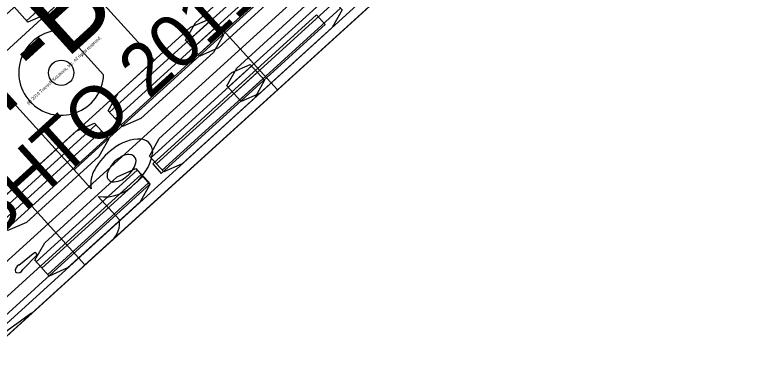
# Model space of a CAD drawing. Extents: x 1639988 to 1641860, y 841974 to 844187.
# Drawn here: x 1640775.68 to 1640795.46, y 844100.65 to 844109.81 of the extents above; entities that cross this region are included whole.
import ezdxf

# ---------------------------------------------------------------- set-up
doc = ezdxf.new("R2010")
doc.units = 0
for name, color, linetype in [('Scratch_Level_1', 7, 'Continuous'), ('Scratch_Level_2', 7, 'Continuous'), ('Scratch_Level_3', 7, 'Continuous'), ('Scratch_Level_4', 7, 'Continuous'), ('Scratch_Level_5', 7, 'Continuous'), ('Scratch_Level_6', 7, 'Continuous')]:
    doc.layers.add(name, color=color, linetype=linetype)

msp = doc.modelspace()

# ---------------------------------------------------------------- linework, layer by layer
at = {"layer": 'Scratch_Level_1'}
for p, q in [((1640777.573, 844103.088), (1640809.032, 844131.664)), ((1640776.003, 844109.65), (1640778.717, 844112.115)), ((1640777.514, 844110.713), (1640770.05, 844103.933)), ((1640779.442, 844108.591), (1640777.514, 844110.713)), ((1640778.239, 844107.189), (1640780.953, 844109.654)), ((1640778.393, 844107.019), (1640781.107, 844109.484)), ((1640771.858, 844109.38), (1640777.573, 844103.088)), ((1640778.077, 844108.196), (1640776.991, 844109.393)), ((1640778.547, 844106.849), (1640781.261, 844109.315)), ((1640771.978, 844101.811), (1640779.442, 844108.591)), ((1640779.348, 844105.967), (1640782.062, 844108.433)), ((1640779.502, 844105.798), (1640782.216, 844108.263)), ((1640779.656, 844105.628), (1640782.37, 844108.093)), ((1640775.155, 844104.387), (1640777.869, 844106.852)), ((1640775.309, 844104.217), (1640778.023, 844106.683)), ((1640775.463, 844104.048), (1640778.177, 844106.513)), ((1640776.264, 844103.166), (1640778.978, 844105.631)), ((1640776.418, 844102.996), (1640779.132, 844105.461)), ((1640776.572, 844102.826), (1640779.286, 844105.292)), ((1640777.573, 844103.088), (1640777.573, 844103.088))]:
    msp.add_line(p, q, dxfattribs=at)
msp.add_lwpolyline([(1640808.793, 844131.447), (1640706.365, 844038.416), (1640702.379, 844034.843), (1640698.36, 844031.302), (1640694.302, 844027.802), (1640690.201, 844024.347), (1640686.055, 844020.942), (1640681.863, 844017.59), (1640677.628, 844014.295), (1640673.351, 844011.058), (1640669.032, 844007.881), (1640664.674, 844004.765), (1640660.276, 844001.71), (1640655.842, 843998.712), (1640651.385, 843995.755), (1640642.436, 843989.91), (1640624.5, 843978.327)], dxfattribs=at)
for points in [[(1640776.041, 844109.608), (1640775.657, 844110.031), (1640775.921, 844110.504), (1640777.875, 844112.279), (1640778.371, 844112.496), (1640778.755, 844112.073), (1640778.491, 844111.6), (1640776.537, 844109.825)], [(1640778.585, 844106.807), (1640778.201, 844107.231), (1640778.465, 844107.703), (1640780.419, 844109.478), (1640780.915, 844109.696), (1640781.299, 844109.273), (1640781.035, 844108.8), (1640779.081, 844107.025)], [(1640779.695, 844105.586), (1640779.31, 844106.009), (1640779.574, 844106.482), (1640781.528, 844108.257), (1640782.024, 844108.475), (1640782.409, 844108.051), (1640782.145, 844107.579), (1640780.19, 844105.803)], [(1640775.501, 844104.006), (1640775.116, 844104.429), (1640775.38, 844104.902), (1640777.335, 844106.677), (1640777.83, 844106.894), (1640778.215, 844106.471), (1640777.951, 844105.998), (1640775.997, 844104.223)], [(1640776.61, 844102.784), (1640776.226, 844103.208), (1640776.49, 844103.68), (1640778.444, 844105.456), (1640778.94, 844105.673), (1640779.324, 844105.25), (1640779.06, 844104.777), (1640777.106, 844103.002)]]:
    msp.add_lwpolyline(points, close=True, dxfattribs=at)
msp.add_circle((1640776.936, 844108.251), 0.34, dxfattribs=at)
msp.add_arc((1640776.936, 844108.251), 1.143, 87.2506, 357.2506, dxfattribs=at)
at = {"layer": 'Scratch_Level_2'}
for p, q in [((1640780.324, 844109.082), (1640783.038, 844111.548)), ((1640780.478, 844108.913), (1640783.192, 844111.378)), ((1640780.632, 844108.743), (1640783.346, 844111.209)), ((1640781.433, 844107.861), (1640784.147, 844110.326)), ((1640781.587, 844107.691), (1640784.301, 844110.157)), ((1640781.741, 844107.522), (1640784.455, 844109.987)), ((1640774.37, 844108.845), (1640777.281, 844105.64)), ((1640775.792, 844103.081), (1640776.225, 844103.422)), ((1640776.285, 844103.355), (1640775.905, 844102.957)), ((1640776.225, 844103.422), (1640776.285, 844103.355)), ((1640776.138, 844101.784), (1640767.856, 844095.829))]:
    msp.add_line(p, q, dxfattribs=at)
for points in [[(1640816.233, 844149.658), (1640816.219, 844149.674), (1640816.166, 844149.627), (1640811.971, 844145.817), (1640777.039, 844114.086), (1640779.897, 844110.941), (1640782.754, 844107.795), (1640817.686, 844139.525), (1640821.88, 844143.336), (1640821.933, 844143.384), (1640821.918, 844143.4)], [(1640821.873, 844143.329), (1640711.577, 844043.147), (1640707.605, 844039.571), (1640703.608, 844036.018), (1640699.578, 844032.494), (1640693.5, 844027.235), (1640689.408, 844023.771), (1640685.265, 844020.368), (1640681.075, 844017.026), (1640676.839, 844013.744), (1640672.558, 844010.522), (1640668.235, 844007.361), (1640663.871, 844004.261), (1640659.466, 844001.222), (1640655.021, 843998.244), (1640650.538, 843995.327), (1640648.282, 843993.891), (1640639.353, 843988.021), (1640630.409, 843982.187), (1640612.503, 843970.59)], [(1640773.908, 844109.353), (1640774.369, 844108.846), (1640774.546, 844109.005), (1640782.216, 844115.972), (1640783.672, 844114.37), (1640785.128, 844112.767), (1640777.458, 844105.8), (1640777.282, 844105.639), (1640777.743, 844105.132)], [(1640777.932, 844104.923), (1640778.501, 844104.297)], [(1640778.304, 844103.752), (1640774.472, 844100.272), (1640775.374, 844099.881), (1640775.375, 844099.881), (1640775.41, 844099.897), (1640775.411, 844099.897), (1640775.411, 844099.897), (1640775.471, 844099.951), (1640775.471, 844099.952), (1640775.248, 844100.22), (1640775.325, 844100.29), (1640775.999, 844099.93), (1640776, 844099.928), (1640775.912, 844099.849), (1640775.908, 844099.849), (1640775.519, 844099.924), (1640775.516, 844099.924), (1640775.451, 844099.866)]]:
    msp.add_lwpolyline(points, dxfattribs=at)
for points in [[(1640780.67, 844108.701), (1640780.285, 844109.125), (1640780.55, 844109.597), (1640782.504, 844111.372), (1640783, 844111.59), (1640783.384, 844111.166), (1640783.12, 844110.694), (1640781.166, 844108.919)], [(1640781.779, 844107.48), (1640781.395, 844107.903), (1640781.659, 844108.376), (1640783.613, 844110.151), (1640784.109, 844110.369), (1640784.494, 844109.945), (1640784.229, 844109.472), (1640782.275, 844107.697)]]:
    msp.add_lwpolyline(points, close=True, dxfattribs=at)
for centre, radius, start, end in [((1640779.057, 844105.331), 1.136, 88.0146, 129.5353), ((1640779.052, 844106.123), 0.346, 345.6433, 82.6563), ((1640779.352, 844104.809), 1.73, 126.0772, 150.8757), ((1640778.879, 844105.334), 0.732, 117.4244, 163.6589), ((1640778.753, 844105.689), 0.362, 76.5472, 125.5881), ((1640778.777, 844105.88), 0.172, 342.5522, 69.7028), ((1640778.006, 844106.35), 1.416, 310.1787, 347.2466), ((1640778.298, 844105.996), 0.664, 307.1544, 345.3761), ((1640778.459, 844105.265), 0.729, 148.0591, 190.5731), ((1640778.336, 844105.484), 0.169, 160.6849, 260.8036), ((1640778.334, 844105.84), 0.522, 267.256, 314.4201), ((1640778.093, 844106.048), 1.136, 261.8805, 316.6718), ((1640777.888, 844104.21), 0.619, 312.2486, 8.0903), ((1640775.881, 844102.921), 0.184, 119.2038, 191.0958), ((1640775.765, 844103.028), 0.157, 245.7966, 332.9062)]:
    msp.add_arc(centre, radius, start, end, dxfattribs=at)
at = {"layer": 'Scratch_Level_3'}
for p, q in [((1640780.324, 844109.082), (1640783.038, 844111.548)), ((1640780.478, 844108.913), (1640783.192, 844111.378)), ((1640780.632, 844108.743), (1640783.346, 844111.209)), ((1640781.433, 844107.861), (1640784.147, 844110.326)), ((1640781.587, 844107.691), (1640784.301, 844110.157)), ((1640781.741, 844107.522), (1640784.455, 844109.987)), ((1640774.37, 844108.845), (1640777.281, 844105.64)), ((1640775.792, 844103.081), (1640776.225, 844103.422)), ((1640776.285, 844103.355), (1640775.905, 844102.957)), ((1640776.225, 844103.422), (1640776.285, 844103.355)), ((1640776.138, 844101.784), (1640767.856, 844095.829))]:
    msp.add_line(p, q, dxfattribs=at)
for points in [[(1640816.233, 844149.658), (1640816.219, 844149.674), (1640816.166, 844149.627), (1640811.971, 844145.817), (1640777.039, 844114.086), (1640779.897, 844110.941), (1640782.754, 844107.795), (1640817.686, 844139.525), (1640821.88, 844143.336), (1640821.933, 844143.384), (1640821.918, 844143.4)], [(1640821.879, 844143.334), (1640711.577, 844043.147), (1640707.605, 844039.571), (1640703.608, 844036.018), (1640699.578, 844032.494), (1640693.5, 844027.235), (1640689.408, 844023.771), (1640685.265, 844020.368), (1640681.075, 844017.026), (1640676.839, 844013.744), (1640672.558, 844010.522), (1640668.235, 844007.361), (1640663.871, 844004.261), (1640659.466, 844001.222), (1640655.021, 843998.244), (1640650.538, 843995.327), (1640648.282, 843993.891), (1640639.353, 843988.021), (1640630.409, 843982.187), (1640612.503, 843970.59)], [(1640773.908, 844109.353), (1640774.369, 844108.846), (1640774.546, 844109.005), (1640782.216, 844115.972), (1640783.672, 844114.37), (1640785.128, 844112.767), (1640777.458, 844105.8), (1640777.282, 844105.639), (1640777.743, 844105.132)], [(1640777.932, 844104.923), (1640778.501, 844104.297)], [(1640778.304, 844103.752), (1640774.472, 844100.272), (1640775.374, 844099.881), (1640775.375, 844099.881), (1640775.41, 844099.897), (1640775.411, 844099.897), (1640775.411, 844099.897), (1640775.471, 844099.951), (1640775.471, 844099.952), (1640775.248, 844100.22), (1640775.325, 844100.29), (1640775.999, 844099.93), (1640776, 844099.928), (1640775.912, 844099.849), (1640775.908, 844099.849), (1640775.519, 844099.924), (1640775.516, 844099.924), (1640775.451, 844099.866)]]:
    msp.add_lwpolyline(points, dxfattribs=at)
for points in [[(1640780.67, 844108.701), (1640780.285, 844109.125), (1640780.55, 844109.597), (1640782.504, 844111.372), (1640783, 844111.59), (1640783.384, 844111.166), (1640783.12, 844110.694), (1640781.166, 844108.919)], [(1640781.779, 844107.48), (1640781.395, 844107.903), (1640781.659, 844108.376), (1640783.613, 844110.151), (1640784.109, 844110.369), (1640784.494, 844109.945), (1640784.229, 844109.472), (1640782.275, 844107.697)]]:
    msp.add_lwpolyline(points, close=True, dxfattribs=at)
for centre, radius, start, end in [((1640779.057, 844105.331), 1.136, 88.0146, 129.5353), ((1640779.052, 844106.123), 0.346, 345.6433, 82.6563), ((1640779.352, 844104.809), 1.73, 126.0772, 150.8757), ((1640778.879, 844105.334), 0.732, 117.4244, 163.6589), ((1640778.753, 844105.689), 0.362, 76.5472, 125.5881), ((1640778.777, 844105.88), 0.172, 342.5522, 69.7028), ((1640778.006, 844106.35), 1.416, 310.1787, 347.2466), ((1640778.298, 844105.996), 0.664, 307.1544, 345.3761), ((1640778.459, 844105.265), 0.729, 148.0591, 190.5731), ((1640778.336, 844105.484), 0.169, 160.6849, 260.8036), ((1640778.334, 844105.84), 0.522, 267.256, 314.4201), ((1640778.093, 844106.048), 1.136, 261.8805, 316.6718), ((1640777.888, 844104.21), 0.619, 312.2486, 8.0903), ((1640775.881, 844102.921), 0.184, 119.2038, 191.0958), ((1640775.765, 844103.028), 0.157, 245.7966, 332.9062)]:
    msp.add_arc(centre, radius, start, end, dxfattribs=at)
at = {"layer": 'Scratch_Level_4'}
msp.add_line((1640765.894, 844094.481), (1640792.862, 844118.977), dxfattribs=at)
for points in [[(1640794.762, 844118.702), (1640731.801, 844061.511), (1640716.025, 844047.15), (1640708.096, 844039.978), (1640700.164, 844032.774), (1640696.182, 844029.177), (1640694.17, 844027.4), (1640692.142, 844025.64), (1640690.1, 844023.895), (1640688.044, 844022.166), (1640685.973, 844020.453), (1640683.889, 844018.756), (1640681.792, 844017.074), (1640677.559, 844013.757), (1640673.278, 844010.502), (1640668.952, 844007.311), (1640664.585, 844004.185), (1640660.181, 844001.125), (1640655.74, 843998.13), (1640651.263, 843995.2), (1640646.749, 843992.333), (1640637.704, 843986.649), (1640628.694, 843980.932)], [(1640766.721, 844093.57), (1640768.852, 844095.506), (1640769.246, 844095.524), (1640771.836, 844097.877), (1640771.892, 844098.267), (1640787.476, 844112.423), (1640787.751, 844112.333), (1640790.342, 844114.687), (1640790.279, 844114.969), (1640793.689, 844118.066)]]:
    msp.add_lwpolyline(points, dxfattribs=at)
for points in [[(1640779.397, 844105.798), (1640779.629, 844105.543), (1640784.04, 844109.55), (1640783.808, 844109.805)], [(1640779.094, 844105.523), (1640779.326, 844105.268), (1640774.914, 844101.26), (1640774.683, 844101.516)]]:
    msp.add_lwpolyline(points, close=True, dxfattribs=at)
at = {"layer": 'Scratch_Level_5'}
msp.add_line((1640765.894, 844094.481), (1640792.862, 844118.977), dxfattribs=at)
for points in [[(1640794.753, 844118.694), (1640731.801, 844061.511), (1640716.025, 844047.15), (1640708.096, 844039.978), (1640700.164, 844032.774), (1640696.182, 844029.177), (1640694.17, 844027.4), (1640692.142, 844025.64), (1640690.1, 844023.895), (1640688.044, 844022.166), (1640685.973, 844020.453), (1640683.889, 844018.756), (1640681.792, 844017.074), (1640677.559, 844013.757), (1640673.278, 844010.502), (1640668.952, 844007.311), (1640664.585, 844004.185), (1640660.181, 844001.125), (1640655.74, 843998.13), (1640651.263, 843995.2), (1640646.749, 843992.333), (1640637.704, 843986.649), (1640628.694, 843980.932)], [(1640766.721, 844093.57), (1640768.852, 844095.506), (1640769.246, 844095.524), (1640771.836, 844097.877), (1640771.892, 844098.267), (1640787.476, 844112.423), (1640787.751, 844112.333), (1640790.342, 844114.687), (1640790.279, 844114.969), (1640793.689, 844118.066)]]:
    msp.add_lwpolyline(points, dxfattribs=at)
for points in [[(1640779.397, 844105.798), (1640779.629, 844105.543), (1640784.04, 844109.55), (1640783.808, 844109.805)], [(1640779.094, 844105.523), (1640779.326, 844105.268), (1640774.914, 844101.26), (1640774.683, 844101.516)]]:
    msp.add_lwpolyline(points, close=True, dxfattribs=at)
at = {"layer": 'Scratch_Level_6'}
msp.add_line((1640765.894, 844094.481), (1640792.862, 844118.977), dxfattribs=at)
for points in [[(1640794.776, 844118.715), (1640731.801, 844061.511), (1640716.025, 844047.15), (1640708.096, 844039.978), (1640700.164, 844032.774), (1640696.182, 844029.177), (1640694.17, 844027.4), (1640692.142, 844025.64), (1640690.1, 844023.895), (1640688.044, 844022.166), (1640685.973, 844020.453), (1640683.889, 844018.756), (1640681.792, 844017.074), (1640677.559, 844013.757), (1640673.278, 844010.502), (1640668.952, 844007.311), (1640664.585, 844004.185), (1640660.181, 844001.125), (1640655.74, 843998.13), (1640651.263, 843995.2), (1640646.749, 843992.333), (1640637.704, 843986.649), (1640628.694, 843980.932)], [(1640766.721, 844093.57), (1640768.852, 844095.506), (1640769.246, 844095.524), (1640771.836, 844097.877), (1640771.892, 844098.267), (1640787.476, 844112.423), (1640787.751, 844112.333), (1640790.342, 844114.687), (1640790.279, 844114.969), (1640793.689, 844118.066)]]:
    msp.add_lwpolyline(points, dxfattribs=at)
for points in [[(1640779.397, 844105.798), (1640779.629, 844105.543), (1640784.04, 844109.55), (1640783.808, 844109.805)], [(1640779.094, 844105.523), (1640779.326, 844105.268), (1640774.914, 844101.26), (1640774.683, 844101.516)]]:
    msp.add_lwpolyline(points, close=True, dxfattribs=at)

# ---------------------------------------------------------------- texts
at = {"layer": 'Scratch_Level_4'}
for s, height, p in [('AASHTO 2011 (US)', 1.41667, (1640773.141, 844101.923)), ('CITY-BUS', 2.125, (1640771.574, 844103.61)), ('(c) 2019 Transoft Solutions, Inc. All rights reserved.', 0.085, (1640776.052, 844107.391))]:
    msp.add_text(s, height=height, rotation=42.2506, dxfattribs=at).set_placement(p)
at = {"layer": 'Scratch_Level_5'}
for s, height, p in [('AASHTO 2011 (US)', 1.41667, (1640773.141, 844101.923)), ('CITY-BUS', 2.125, (1640771.574, 844103.61)), ('(c) 2019 Transoft Solutions, Inc. All rights reserved.', 0.085, (1640776.052, 844107.391))]:
    msp.add_text(s, height=height, rotation=42.2506, dxfattribs=at).set_placement(p)
at = {"layer": 'Scratch_Level_6'}
for s, height, p in [('AASHTO 2011 (US)', 1.41667, (1640773.141, 844101.923)), ('CITY-BUS', 2.125, (1640771.574, 844103.61)), ('(c) 2019 Transoft Solutions, Inc. All rights reserved.', 0.085, (1640776.052, 844107.391))]:
    msp.add_text(s, height=height, rotation=42.2506, dxfattribs=at).set_placement(p)

doc.saveas('drawing.dxf')
